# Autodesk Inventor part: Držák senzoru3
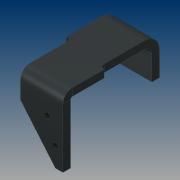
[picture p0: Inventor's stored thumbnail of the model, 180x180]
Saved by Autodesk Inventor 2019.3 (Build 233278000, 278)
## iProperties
Created: 2019-04
Part Number: Držák senzoru3
Material: Ocel, měkká, svařovaná
Document SubType Name: Plech
Designer: B-hon
Density: 7.85 g/cm^3
Sheet Metal Rule: Výchozí_mm
Appearance: Železo – šedé
Author: B-hon
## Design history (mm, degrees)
node "Plocha1"
  sketch "Náčrt1"
    geometry: L1 (0, 0)-(50, 0); L2 (50, 0)-(50, 26); L3 (50, 26)-(0, 26); L4 (0, 26)-(0, 0)
    constraints: 8 end point, 2 parallel, 1 horizontal, 1 perpendicular
    dimensions: "d0" = 50 distance of L3.end L2.end; "d1" = 26 distance of L2.end L1.end
node "Obruba1"
node "Obruba2"
sketch "Náčrt5"
  geometry: L1 (50, 0)-(0, 0) reference; L2 (50, 63)-(50, 0) reference; 2 further points
  dimensions: "d33" = 20 distance from line of L1 point (42, 20); "d34" = 8 distance from line of L2 point (42, 20)
hole "Díra2" sketch "Náčrt5" at (42, 20) diameter "d35" = 6; stored, may be unused: countersink angle "d39" = 90 deg, drill point angle "d41" = 118 deg; dims "d36" = 6, "d37" = 4, "d38" = 2, "d40" = 8 (= Tloušťka)
sketch "Náčrt6"
  geometry: L1 (60.347, 27.171)-(45, 27.171); L2 (45, 27.171)-(45, -47.75); L3 (45, -47.75)-(60.347, -47.75); L4 (60.347, -47.75)-(60.347, 27.171); L5 (50, -91.5)-(0, -91.5) reference; L6 (50, 16)-(0, 16) reference; L7 (50, 0)-(50, -81.5) reference; L8 (-14.918, -106.157)-(5, -106.157); L9 (5, -106.157)-(5, -37.75); L10 (5, -37.75)-(-14.918, -37.75); L11 (-14.918, -37.75)-(-14.918, -106.157); L12 (0, -81.5)-(0, 0) reference
  constraints: 16 end point, 4 parallel, 2 horizontal, 2 perpendicular
  dimensions: "d42" = 107.5 distance between parallel lines of L5 L6 (derived); "d43" = 63.75 distance between parallel lines of L6 L3 (computed from d42); "d44" = 5 distance between parallel lines of L7 L2; "d45" = 53.75 distance between parallel lines of L10 L5 (= 0.5 x d42); "d46" = 5 distance between parallel lines of L9 L12
extrude "Vysunutí1" cut sketch "Náčrt6" extent not by distance; stored distance "d47" = 10; taper "d48" = 0 deg
fillet "Zaoblení1" dims "d49" = 5
sketch "Náčrt7"
  geometry: L1 (0, 0)-(-45, 0) reference; L2 (-8, 0)-(-57.664, 59.187); L3 (-57.664, 59.187)-(-66.474, -14.058); L4 (-66.474, -14.058)-(-8, 0); 1 further point
  constraints: 6 end point, 1 point on line
  dimensions: "d50" = 50 deg angle of L1 L2; "d51" = 8 distance of L1.start L2.start
extrude "Vysunutí2" cut sketch "Náčrt7" distance "d52" = 10; taper "d53" = 0 deg
sketch "Náčrt8" dims "d54" = 50
  geometry: C1 r 3 at (-8, 20) reference; 3 further points
  constraints: 1 coincident, 3 other
hole "Díra3" sketch "Náčrt8" at (-16.139, 43.638) diameter "d56" = 6; stored, may be unused: countersink angle "d60" = 90 deg, drill point angle "d62" = 118 deg; dims "d57" = 6, "d58" = 4, "d59" = 2, "d61" = 8 (= Tloušťka)
node "Těleso1"
feature "Deska1" dims "d2" = 8 (= Tloušťka)
sketch "Náčrt2"
  geometry: L1 through (-25, 0) direction (1, 0); L2 through (0, 45.75) direction (0, 1); L3 (0, 91.5)-(-50, 91.5); L4 (-50, 91.5)-(-50, 0)
  constraints: 6 end point, 1 horizontal, 1 perpendicular, 1 vertical
feature "Deska2" dims "d2" = 8 (= Tloušťka), "d3" = 8 (= ŠířkaVýštipu), "d4" = 4 (= HloubkaVýštipu), "d5" = 16 (= MinimálníZbytek), "d6" = 8 (= PřechodovýPoloměr), "d7" = 107.5, "d8" = 90 deg, "d9" = 8 (= PoloměrOhybu), "d10" = 32 (= VelikostRohovéhoVýštipu), "d11" = 8 (= VelikostMezery), "d12" = 8 (= VelikostJacobihoPoloměru), "MezeraVystřižení" = 0.01
feature "Ohyb1" dims "d2" = 8 (= Tloušťka), "d3" = 8 (= ŠířkaVýštipu), "d4" = 4 (= HloubkaVýštipu), "d5" = 16 (= MinimálníZbytek), "d6" = 8 (= PřechodovýPoloměr), "d7" = 107.5, "d8" = 90 deg, "d9" = 8 (= PoloměrOhybu), "MezeraVystřižení" = 0.01
feature "Roh1" dims "d7" = 107.5, "d8" = 90 deg, "d10" = 32 (= VelikostRohovéhoVýštipu), "d11" = 8 (= VelikostMezery), "d12" = 8 (= VelikostJacobihoPoloměru)
sketch "Náčrt4"
  geometry: L1 through (25, 0) direction (-1, -2.29e-34); L2 through (0, -36.5) direction (0, -1); L3 (0, -73)-(50, -73); L4 (50, -73)-(50, 0)
  constraints: 6 end point, 1 horizontal, 1 perpendicular, 1 vertical
feature "Deska3" dims "d2" = 8 (= Tloušťka), "d23" = 8 (= ŠířkaVýštipu), "d24" = 4 (= HloubkaVýštipu), "d25" = 16 (= MinimálníZbytek), "d26" = 8 (= PřechodovýPoloměr), "d27" = 73, "d28" = 90 deg, "d29" = 2, "d30" = 32 (= VelikostRohovéhoVýštipu), "d31" = 8 (= VelikostMezery), "d32" = 8 (= VelikostJacobihoPoloměru), "MezeraVystřižení" = 0.01
feature "Ohyb2" dims "d2" = 8 (= Tloušťka), "d23" = 8 (= ŠířkaVýštipu), "d24" = 4 (= HloubkaVýštipu), "d25" = 16 (= MinimálníZbytek), "d26" = 8 (= PřechodovýPoloměr), "d27" = 73, "d28" = 90 deg, "d29" = 2, "MezeraVystřižení" = 0.01
feature "Roh2" dims "d27" = 73, "d28" = 90 deg, "d30" = 32 (= VelikostRohovéhoVýštipu), "d31" = 8 (= VelikostMezery), "d32" = 8 (= VelikostJacobihoPoloměru)
other parameters: "Tloušťka" = 8 (derived), "KSoučinitel" = 4.4, "PoloměrOhybu" = 8 (= Tloušťka), "ŠířkaVýštipu" = 8 (= Tloušťka), "HloubkaVýštipu" = 4 (= 0.5 x Tloušťka), "VelikostRohovéhoVýštipu" = 32 (= 4 x Tloušťka), "MinimálníZbytek" = 16 (= 2 x Tloušťka), "PřechodovýPoloměr" = 8 (= PoloměrOhybu), "VelikostJacobihoPoloměru" = 8 (= PoloměrOhybu), "VelikostMezery" = 8 (= Tloušťka)
